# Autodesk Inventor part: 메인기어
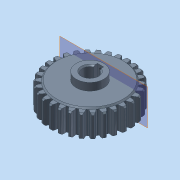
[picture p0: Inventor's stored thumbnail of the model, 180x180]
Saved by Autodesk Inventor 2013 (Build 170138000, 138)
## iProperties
Created: 2011-08
Part Number: 메인기어
Document SubType Name: Modeling
Designer: KYOUNG IL JANG
Density: 7.86 g/cm^3
Material: 강철, 연강
Mass: 423.556 g
Surface Area: 135.188 cm^2
Volume: 53.8876 cm^3
Description: 잇수:30 / PCD:60
Author: mm
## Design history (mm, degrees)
sketch "스케치1"
  geometry: C1 r 27.5 at (0, 0); A1 r 27.5 centre (0, 0) between (2.757, 27.361) and (-2.757, 27.361); A2 r 32 centre (0, 0) between (0.737, 31.992) and (-0.737, 31.992); A3 r 1.004 centre (-2.903, 28.355) between (-2.757, 27.361) and (-1.899, 28.332); A4 r 7.498 centre (5.568, 27.656) between (-1.648, 29.691) and (-1.899, 28.332); A5 r 12.465 centre (10.34, 26.276) between (-0.737, 31.992) and (-1.648, 29.691); A6 r 1.004 centre (2.903, 28.355) between (1.899, 28.332) and (2.757, 27.361); A7 r 7.498 centre (-5.568, 27.656) between (1.899, 28.332) and (1.648, 29.691); A8 r 12.465 centre (-10.34, 26.276) between (1.648, 29.691) and (0.737, 31.992); 1 further point
  constraints: 16 point on circle, 9 centre point, 1 coincident, 1 concentric
extrude "돌출1" new body sketch "스케치1" stored distance "d0" = 20; taper "d1" = 0 deg
extrude "돌출2" join sketch "스케치1" stored distance "d2" = 18; taper "d3" = 0 deg
chamfer "모따기1" distance "d4" = 1; stored, may be unused: second distance "d5" = 2, angle "d6" = 45 deg
sketch "스케치2"
  geometry: 1 further point
hole "구멍1" sketch "스케치2" at (0, 0) diameter "d10" = 12; stored, may be unused: countersink angle "d14" = 90 deg, drill point angle "d16" = 118 deg; dims "d11" = 6, "d12" = 4, "d13" = 2, "d15" = 8
sketch "스케치3"
  geometry: L1 (-2.5, 5.454)-(-2.5, 8.5); L2 (-2.5, 8.5)-(2.5, 8.5); L3 (2.5, 8.5)-(2.5, 5.454); C1 r 6 at (0, 0); A1 r 6 centre (0, 0) between (-2.5, 5.454) and (2.5, 5.454) reference; 1 further point
  constraints: 6 end point, 2 point on circle, 2 vertical, 1 centre point, 1 coincident, 1 horizontal, 1 parallel
  dimensions: "d17" = 2.5 distance edge to line of A1 L2; "d18" = 5 distance of L1.end L2.end; "d27" = 12 diameter of C1
extrude "돌출3" cut sketch "스케치3" stored distance "d19" = 10; taper "d20" = 0 deg
chamfer "모따기2" distance "d21" = 1; stored, may be unused: second distance "d22" = 2, angle "d23" = 45 deg
chamfer "모따기3" distance "d24" = 1; stored, may be unused: second distance "d25" = 2, angle "d26" = 45 deg
sketch "스케치4"
  geometry: L1 (2.5, 8.5)-(2.5, 5.454) reference; L2 (-2.5, 8.5)-(2.5, 8.5) reference; L3 (-2.5, 5.454)-(-2.5, 8.5) reference; C1 r 11 at (0, 0); A1 r 6 centre (0, 0) between (-2.5, 5.454) and (2.5, 5.454) reference; 1 further point
  constraints: 1 centre point, 1 coincident
  dimensions: "d28" = 22 diameter of C1
extrude "돌출4" join sketch "스케치4" distance "d30" = 6; taper "d31" = 0 deg
chamfer "모따기4" distance "d40" = 1; stored, may be unused: second distance "d41" = 2, angle "d42" = 45 deg
node "작업 평면1"
sketch "스케치5"
  geometry: L1 (11, 6)-(-11, 6) reference; 2 further points
  constraints: 1 vertical alignment
  dimensions: "d32" = 3 distance from line of point (0, 3) L1
hole "구멍2" sketch "스케치5" at (0, 3) diameter "d33" = 2.459; stored, may be unused: countersink angle "d37" = 90 deg, drill point angle "d39" = 118 deg; dims "d34" = 6, "d35" = 4, "d36" = 2, "d38" = 8
node "솔리드1"
pattern_circular "원형 패턴1" dims angle "d8" = 360 deg
